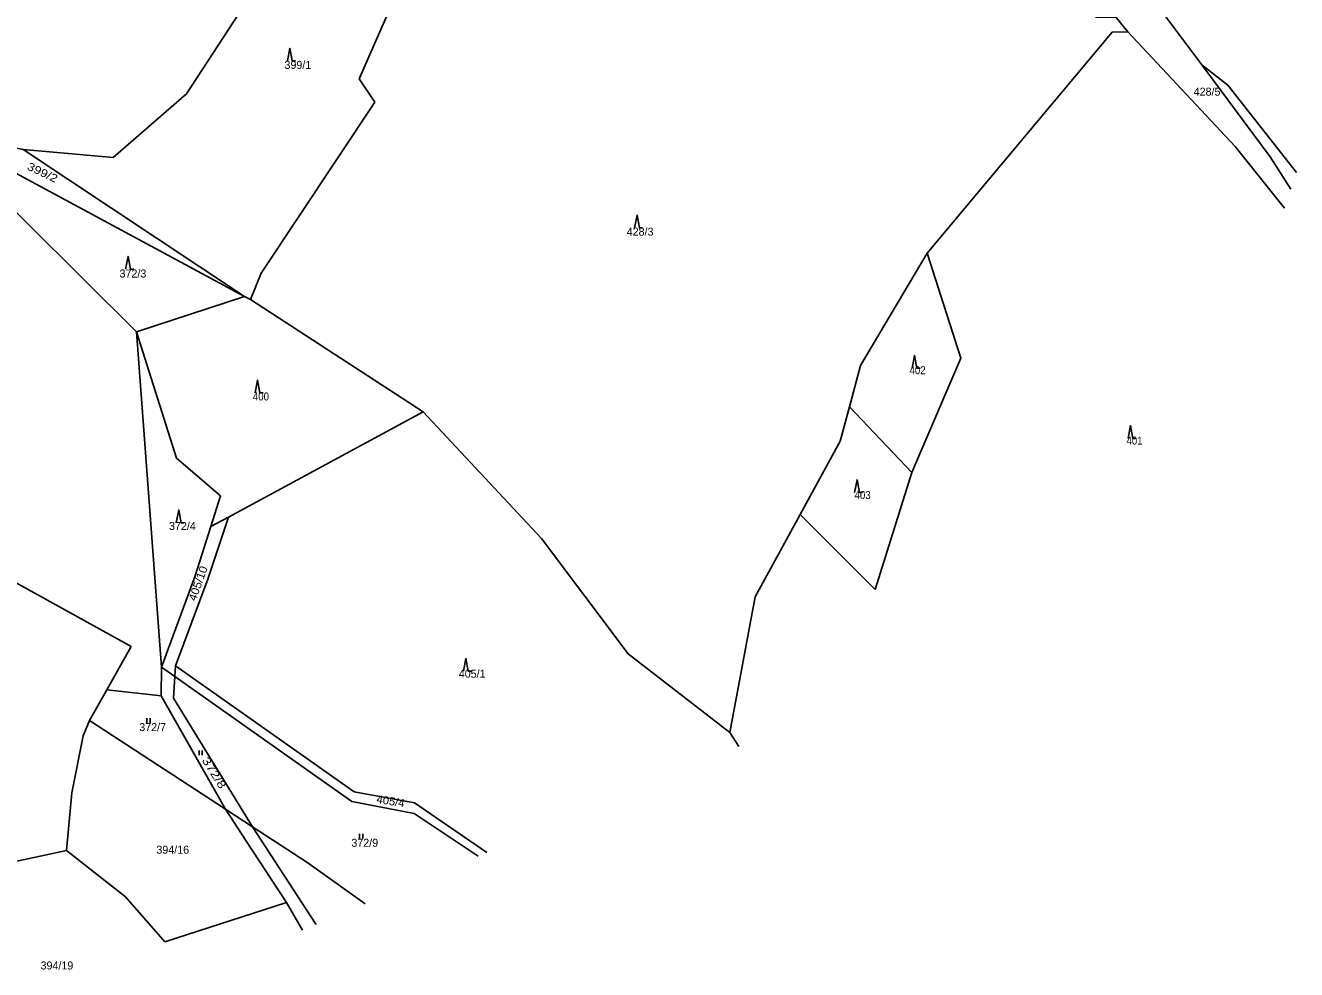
# Model space of a CAD drawing. Extents: x -680102 to -677253, y -1007548 to -1006096.
# Drawn here: x -677710.2 to -677313.2, y -1006764.7 to -1006469.8 of the extents above; entities that cross this region are included whole.
import ezdxf

# ---------------------------------------------------------------- set-up
doc = ezdxf.new("R2010")
doc.units = 0
doc.layers.add('1', color=7, linetype='Continuous', lineweight=25)
doc.layers.add('25', color=7, linetype='Continuous', lineweight=25)
doc.layers.add('18', color=7, linetype='Continuous')

msp = doc.modelspace()

# ---------------------------------------------------------------- linework, layer by layer
at = {"layer": '1'}
for p, q in [((-677590.47, -1006451.07), (-677605.94, -1006486.49)), ((-677334.75, -1006488.41), (-677342.85, -1006482.04)), ((-677321.47, -1006510.83), (-677342.85, -1006482.04)), ((-677605.94, -1006486.49), (-677601.13, -1006493.75)), ((-677313.24, -1006515.67), (-677334.75, -1006488.41)), ((-677601.13, -1006493.75), (-677636.59, -1006547.15)), ((-677739.46, -1006502.05), (-677709.58, -1006531.64)), ((-677315.01, -1006520.89), (-677321.47, -1006510.83)), ((-677636.59, -1006547.15), (-677639.88, -1006555.35)), ((-677641.74, -1006554.43), (-677675.52, -1006565.51)), ((-677646.82, -1006623.37), (-677585.95, -1006590.42)), ((-677549.01, -1006630.03), (-677585.95, -1006590.42)), ((-677433.35, -1006609.4), (-677452.9, -1006588.93)), ((-677433.35, -1006609.4), (-677444.89, -1006645.99)), ((-677653.2, -1006642.78), (-677646.82, -1006623.37)), ((-677652.31, -1006626.32), (-677646.82, -1006623.37)), ((-677444.89, -1006645.99), (-677468.29, -1006622.58)), ((-677521.94, -1006666.05), (-677549.01, -1006630.03)), ((-677677.13, -1006663.73), (-677723.8, -1006638.01)), ((-677667.68, -1006670.27), (-677657.15, -1006641.73)), ((-677663.35, -1006669.81), (-677653.2, -1006642.78)), ((-677482.33, -1006648.31), (-677490.25, -1006690.61)), ((-677490.25, -1006690.61), (-677521.94, -1006666.05)), ((-677667.68, -1006670.27), (-677667.79, -1006679.15)), ((-677607.5, -1006709.18), (-677663.35, -1006669.81)), ((-677667.79, -1006679.15), (-677684.78, -1006677.26)), ((-677664.01, -1006679.95), (-677639.31, -1006720.06)), ((-677647.68, -1006714.61), (-677690.23, -1006686.9)), ((-677487.38, -1006694.98), (-677490.25, -1006690.61)), ((-677695.73, -1006709.46), (-677697.37, -1006727.51)), ((-677588.65, -1006712.63), (-677607.5, -1006709.18)), ((-677566.08, -1006728.11), (-677588.65, -1006712.63)), ((-677639.31, -1006720.06), (-677619.54, -1006750.5)), ((-677697.37, -1006727.51), (-677740.97, -1006736.82)), ((-677678.96, -1006741.96), (-677697.37, -1006727.51)), ((-677604.15, -1006744.14), (-677622.36, -1006731.1)), ((-677666.68, -1006755.98), (-677678.96, -1006741.96)), ((-677623.71, -1006752.37), (-677628.66, -1006743.77)), ((-677619.49, -1006750.59), (-677619.54, -1006750.5))]:
    msp.add_line(p, q, dxfattribs=at)
for points in [[(-677710.93, -1006508.5), (-677682.78, -1006511.05), (-677659.9, -1006491.14), (-677635.46, -1006453.54), (-677616.1, -1006409.05), (-677645.51, -1006395.86), (-677697.86, -1006384.12), (-677718.21, -1006382.38), (-677754.71, -1006390.36), (-677769.19, -1006389.6)], [(-677497.11, -1006447.85), (-677488.02, -1006452.74), (-677478.69, -1006461.9), (-677468.33, -1006464.73), (-677444.49, -1006456.8), (-677376.1, -1006460.68), (-677375.96, -1006467.15), (-677369.62, -1006467.29), (-677365.98, -1006471.74), (-677370.84, -1006471.88), (-677428.55, -1006540.9), (-677449.44, -1006576.04)], [(-677342.85, -1006482.04), (-677361.85, -1006456.57), (-677350.94, -1006445.48)], [(-677365.98, -1006471.74), (-677332.43, -1006507.55), (-677317.03, -1006526.83)], [(-677585.95, -1006590.42), (-677639.88, -1006555.35), (-677641.74, -1006554.43), (-677736.14, -1006503.66), (-677739.46, -1006502.05)], [(-677736.14, -1006503.66), (-677710.93, -1006508.5), (-677641.74, -1006554.43)], [(-677709.58, -1006531.64), (-677675.52, -1006565.51), (-677667.68, -1006670.27)], [(-677428.55, -1006540.9), (-677418.06, -1006573.67), (-677433.35, -1006609.4)], [(-677649.3, -1006616.72), (-677663.02, -1006604.93), (-677675.52, -1006565.51)], [(-677449.44, -1006576.04), (-677452.9, -1006588.93), (-677455.78, -1006599.66)], [(-677455.78, -1006599.66), (-677468.29, -1006622.58), (-677482.33, -1006648.31)], [(-677657.15, -1006641.73), (-677652.31, -1006626.32), (-677649.3, -1006616.72)], [(-677677.13, -1006663.73), (-677684.78, -1006677.26), (-677690.23, -1006686.9)], [(-677667.68, -1006670.27), (-677663.57, -1006673.17), (-677608.28, -1006712.14)], [(-677663.35, -1006669.81), (-677663.57, -1006673.17), (-677664.01, -1006679.95)], [(-677667.79, -1006679.15), (-677647.68, -1006714.61), (-677641.33, -1006724.42)], [(-677690.23, -1006686.9), (-677692.12, -1006691.66), (-677695.73, -1006709.46)], [(-677622.36, -1006731.1), (-677639.31, -1006720.06), (-677647.68, -1006714.61)], [(-677608.28, -1006712.14), (-677588.81, -1006715.95), (-677568.87, -1006729.29)], [(-677641.33, -1006724.42), (-677628.66, -1006743.77), (-677666.68, -1006755.98)]]:
    msp.add_lwpolyline(points, dxfattribs=at)
at = {"layer": '25'}
for p, q in [((-677672.267, -1006687.695), (-677672.267, -1006686.195)), ((-677671.233, -1006687.695), (-677671.233, -1006686.195)), ((-677655.997, -1006697.715), (-677655.997, -1006696.215)), ((-677654.963, -1006697.715), (-677654.963, -1006696.215)), ((-677605.857, -1006723.745), (-677605.857, -1006722.245)), ((-677604.823, -1006723.745), (-677604.823, -1006722.245))]:
    msp.add_line(p, q, dxfattribs=at)
for points in [[(-677628.36, -1006480.88), (-677627.61, -1006476.88), (-677626.86, -1006480.88), (-677625.86, -1006480.88)], [(-677519.96, -1006533.02), (-677519.21, -1006529.02), (-677518.46, -1006533.02), (-677517.46, -1006533.02)], [(-677678.9, -1006545.93), (-677678.15, -1006541.93), (-677677.4, -1006545.93), (-677676.4, -1006545.93)], [(-677433.29, -1006576.83), (-677432.54, -1006572.83), (-677431.79, -1006576.83), (-677430.79, -1006576.83)], [(-677638.47, -1006584.55), (-677637.72, -1006580.55), (-677636.97, -1006584.55), (-677635.97, -1006584.55)], [(-677365.88, -1006598.78), (-677365.13, -1006594.78), (-677364.38, -1006598.78), (-677363.38, -1006598.78)], [(-677451.26, -1006615.66), (-677450.51, -1006611.66), (-677449.76, -1006615.66), (-677448.76, -1006615.66)], [(-677663.08, -1006625.13), (-677662.33, -1006621.13), (-677661.58, -1006625.13), (-677660.58, -1006625.13)], [(-677573.41, -1006671.52), (-677572.66, -1006667.52), (-677571.91, -1006671.52), (-677570.91, -1006671.52)]]:
    msp.add_lwpolyline(points, dxfattribs=at)

# ---------------------------------------------------------------- texts
at = {"layer": '18'}
for s, p in [('399/1', (-677629.3, -1006483.35)), ('428/5', (-677345.38, -1006491.71)), ('428/3', (-677522.43, -1006535.45)), ('372/3', (-677680.81, -1006548.51)), ('372/4', (-677665.37, -1006627.38)), ('405/1', (-677574.87, -1006673.52)), ('372/7', (-677674.66, -1006690.21)), ('394/16', (-677669.31, -1006728.5)), ('372/9', (-677608.42, -1006726.33)), ('394/19', (-677705.48, -1006764.66))]:
    msp.add_text(s, height=2.5, dxfattribs=at).set_placement(p)
for s, rotation, width, p in [('399/2', 334.603, 1.2, (-677709.934, -1006514.656)), ('405/10', 70.501, 1.1, (-677657.011, -1006649.795)), ('372/8', 302.002, 1.3, (-677655.205, -1006699.283)), ('405/4', 350.803, 1.05, (-677600.691, -1006712.595))]:
    msp.add_text(s, height=2.5, rotation=rotation, dxfattribs=dict(at, width=width)).set_placement(p)
at = {"layer": '18', "width": 0.9}
for s, p in [('402', (-677434.11, -1006578.72)), ('400', (-677639.17, -1006586.92)), ('401', (-677366.35, -1006600.7)), ('403', (-677451.27, -1006617.71))]:
    msp.add_text(s, height=2.5, dxfattribs=at).set_placement(p)

doc.saveas('drawing.dxf')
